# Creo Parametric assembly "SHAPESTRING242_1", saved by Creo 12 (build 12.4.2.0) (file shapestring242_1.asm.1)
Units: Custom; MM, KILOGRAM, SECS

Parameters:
  PTC_WM_ITERATION = "0"
  PTC_WM_VERSION = "-.0"
  PTC_WM_LIFECYCLE_STATE = "In Work"
  PTC_WM_LIFECYCLE = "MO_CADDocument"
  PTC_WM_CREATED_BY = "Maximilian Roepper (Z0017RMS: MO)"
  PTC_WM_CREATED_ON = "18-Sep-26 11:36:42 AM"
  PTC_WM_MODIFIED_BY = "Maximilian Roepper (Z0017RMS: MO)"
  PTC_WM_MODIFIED_ON = "18-Sep-26 11:36:46 AM"
  PDMLINKNUMBER = "PDM000071454942"
  PTC_WM_NAME = "shapestring242_1.asm"
  PTC_WM_NUMBER = "PDM000071454942"

Other parameters: WEIGHT, WEIGHT_FACTOR, WEIGHT_ADD, MC_ERRORS, SUPPLIER, ISPOSITIONINGASSEMBLY

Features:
  1. coordinate system
  2. imported feature
  3. component "SHAPESTRING096_1"
  4. component "SHAPESTRING241_1"

Other named items: DRW_VIEW_ORG, ROUGH-GROB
